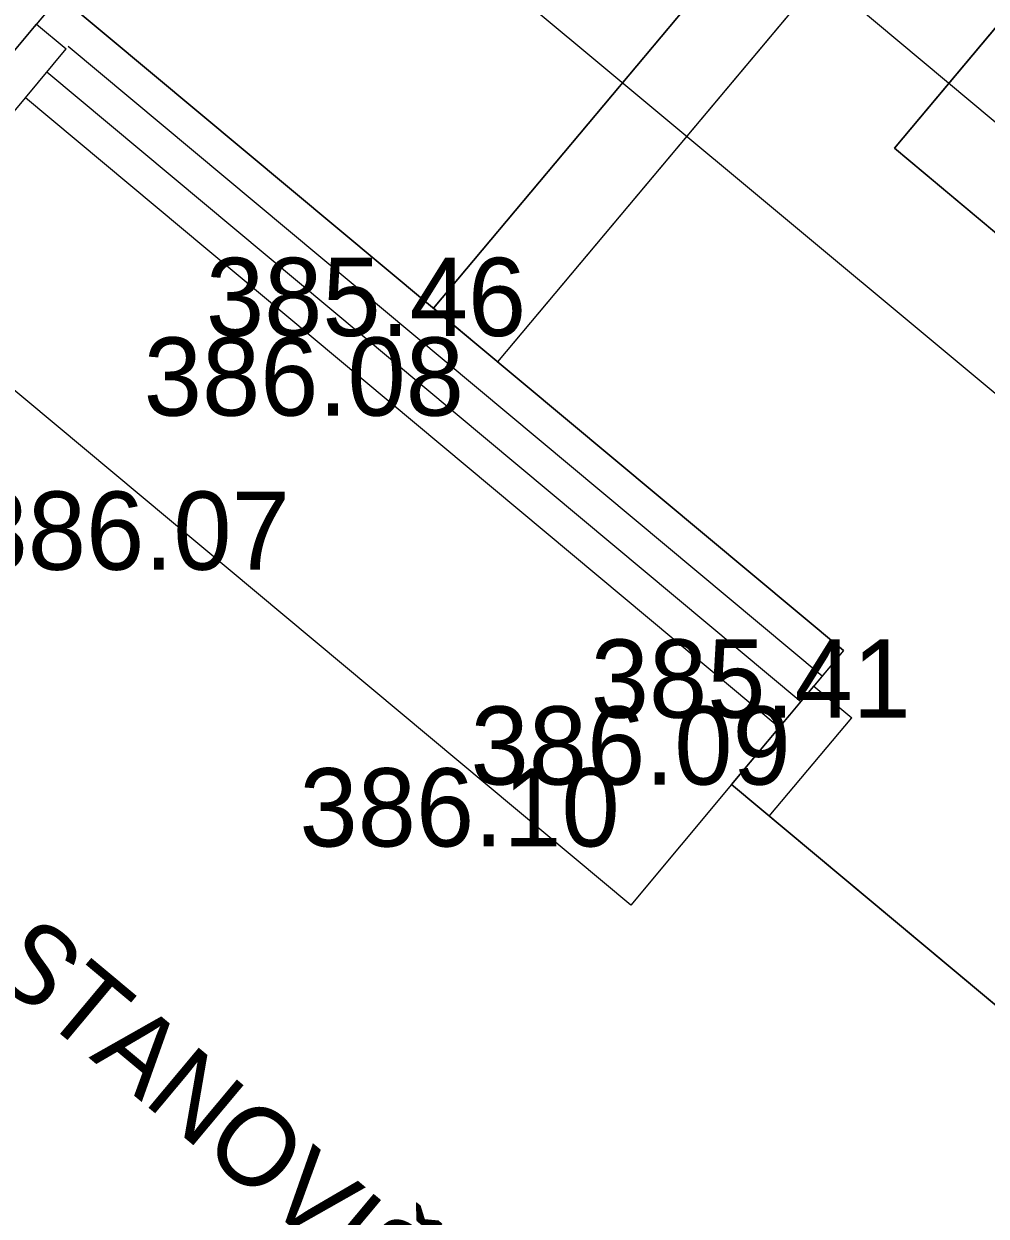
# Model space of a CAD drawing. Extents: x -438233 to -437334, y -1133133 to -1132623.
# Drawn here: x -438109.55 to -438100.33, y -1132995.04 to -1132983.61 of the extents above; entities that cross this region are included whole.
import ezdxf

# ---------------------------------------------------------------- set-up
doc = ezdxf.new("R2010")
doc.units = 0
for name, color, linetype in [('Vrstva 1', 7, 'Continuous'), ('Vrstva 10', 7, 'Continuous'), ('Vrstva 11', 7, 'Continuous'), ('Vrstva 15', 7, 'Continuous'), ('Vrstva 3', 7, 'Continuous'), ('Vrstva 5', 7, 'Continuous'), ('Vrstva 50', 7, 'Continuous'), ('Vrstva 55', 7, 'Continuous')]:
    doc.layers.add(name, color=color, linetype=linetype)

msp = doc.modelspace()

# ---------------------------------------------------------------- linework, layer by layer
at = {"layer": 'Vrstva 1'}
for p, q in [((-438098.32, -1132981.35), (-438101.21, -1132984.8)), ((-438101.21, -1132984.8), (-438075.914, -1133005.992)), ((-438105.306, -1132986.601), (-438105.306, -1132986.601)), ((-438105.902, -1132987.364), (-438105.902, -1132987.364)), ((-438107.57, -1132988.841), (-438107.57, -1132988.841)), ((-438101.62, -1132990.259), (-438101.62, -1132990.259)), ((-438102.771, -1132990.9), (-438102.771, -1132990.9)), ((-438104.41, -1132991.493), (-438104.41, -1132991.493))]:
    msp.add_line(p, q, dxfattribs=at)
at = {"layer": 'Vrstva 10'}
msp.add_lwpolyline([(-438136.916, -1132976.04), (-438130.815, -1132968.777), (-438110.909, -1132985.383), (-438109.206, -1132983.342), (-438101.698, -1132989.616), (-438102.771, -1132990.9), (-438091.189, -1133000.578), (-438097.908, -1133008.583)], close=True, dxfattribs=at)
msp.add_lwpolyline([(-438106.458, -1132981.967), (-438090.957, -1132994.89), (-438086.882, -1132998.283), (-438085.153, -1132999.203), (-438079.851, -1133001.541), (-438076.272, -1133002.948)], dxfattribs=at)
at = {"layer": 'Vrstva 11'}
for p, q in [((-438110.088, -1132984.399), (-438109.43, -1132983.611)), ((-438109.804, -1132984.636), (-438109.146, -1132983.848)), ((-438101.903, -1132989.862), (-438109.125, -1132983.827)), ((-438102.108, -1132990.107), (-438109.33, -1132984.072)), ((-438102.314, -1132990.353), (-438109.536, -1132984.318)), ((-438102.771, -1132990.9), (-438101.982, -1132989.956)), ((-438102.409, -1132991.203), (-438101.62, -1132990.259))]:
    msp.add_line(p, q, dxfattribs=at)
for points in [[(-438101.698, -1132989.616), (-438109.206, -1132983.342), (-438109.43, -1132983.611)], [(-438109.43, -1132983.611), (-438109.146, -1132983.848)], [(-438101.698, -1132989.616), (-438101.982, -1132989.956)], [(-438101.982, -1132989.956), (-438101.62, -1132990.259)]]:
    msp.add_lwpolyline(points, dxfattribs=at)
at = {"layer": 'Vrstva 15'}
for p, q in [((-438100.416, -1132980.116), (-438105.626, -1132986.334)), ((-438099.803, -1132980.63), (-438105.012, -1132986.847))]:
    msp.add_line(p, q, dxfattribs=at)
msp.add_lwpolyline([(-438101.643, -1132979.088), (-438101.288, -1132978.609), (-438098.247, -1132981.16), (-438098.587, -1132981.649), (-438099.803, -1132980.63), (-438105.012, -1132986.847), (-438105.626, -1132986.334), (-438100.416, -1132980.116)], close=True, dxfattribs=at)
at = {"layer": 'Vrstva 5'}
for p, q in [((-438103.737, -1132992.056), (-438110.959, -1132986.021)), ((-438102.771, -1132990.9), (-438103.737, -1132992.056)), ((-438091.189, -1133000.578), (-438102.771, -1132990.9))]:
    msp.add_line(p, q, dxfattribs=at)
at = {"layer": 'Vrstva 50'}
msp.add_lwpolyline([(-438098.32, -1132981.35), (-438073.025, -1133002.541), (-438075.915, -1133005.991), (-438101.21, -1132984.8)], close=True, dxfattribs=at)
at = {"layer": 'Vrstva 55'}
msp.add_lwpolyline([(-438074.959, -1133013.61), (-438076.856, -1133009.846), (-438083.298, -1132998.719), (-438115.192, -1132972.054), (-438146.469, -1132953.711), (-438176.9, -1132931.48)], dxfattribs=at)

# ---------------------------------------------------------------- texts
at = {"layer": 'Vrstva 3'}
for s, p in [('385.46 ', (-438107.806, -1132986.601)), ('386.08 ', (-438108.402, -1132987.364)), ('386.07 ', (-438110.07, -1132988.841)), ('385.41 ', (-438104.12, -1132990.259)), ('386.09 ', (-438105.271, -1132990.9)), ('386.10 ', (-438106.91, -1132991.493))]:
    msp.add_text(s, height=0.75, dxfattribs=at).set_placement(p)
at = {"layer": 'Vrstva 55'}
msp.add_text('AUTOBUSOVÉ STANOVIŠTE', height=0.74999, rotation=320.1027, dxfattribs=at).set_placement((-438115.474, -1132988.046))
msp.add_text('AUTOBUSOVÉ STANOVIŠTE', height=0.74999, rotation=320.1027, dxfattribs=at).set_placement((-438115.474, -1132988.046))

doc.saveas('drawing.dxf')
